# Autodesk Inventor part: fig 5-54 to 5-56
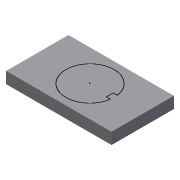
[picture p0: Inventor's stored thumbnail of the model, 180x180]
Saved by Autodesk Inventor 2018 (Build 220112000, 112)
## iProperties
Created: 2005-12
Part Number: fig 5-54 to 5-56
Document SubType Name: Modeling
Designer: CADCIM
Density: 1 g/cm^3
Material: Generic
Appearance: Default
Author: CADCIM
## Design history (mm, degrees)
sketch "Sketch1"
  geometry: L1 (-47.674, -20.831)-(44.057, -20.831); L2 (44.057, -20.831)-(44.057, 33.398); L3 (44.057, 33.398)-(-47.674, 33.398); L4 (-47.674, 33.398)-(-47.674, -20.831)
  constraints: 8 end point, 2 parallel, 1 horizontal, 1 perpendicular
extrude "Extrusion1" new body sketch "Sketch1" distance "d0" = 10; taper "d1" = 0 deg
sketch "Sketch2"
  geometry: L1 (15.359, 9.199)-(18.885, 9.199); L2 (18.885, 3.199)-(15.359, 3.199); L3 (15.359, 3.199)-(15.359, 9.199); A1 r 20.978 centre (-1.877, 6.199) between (18.885, 9.199) and (18.885, 3.199)
  constraints: 6 end point, 2 parallel, 2 point on circle, 1 centre point, 1 horizontal, 1 vertical
body "Solid1"
